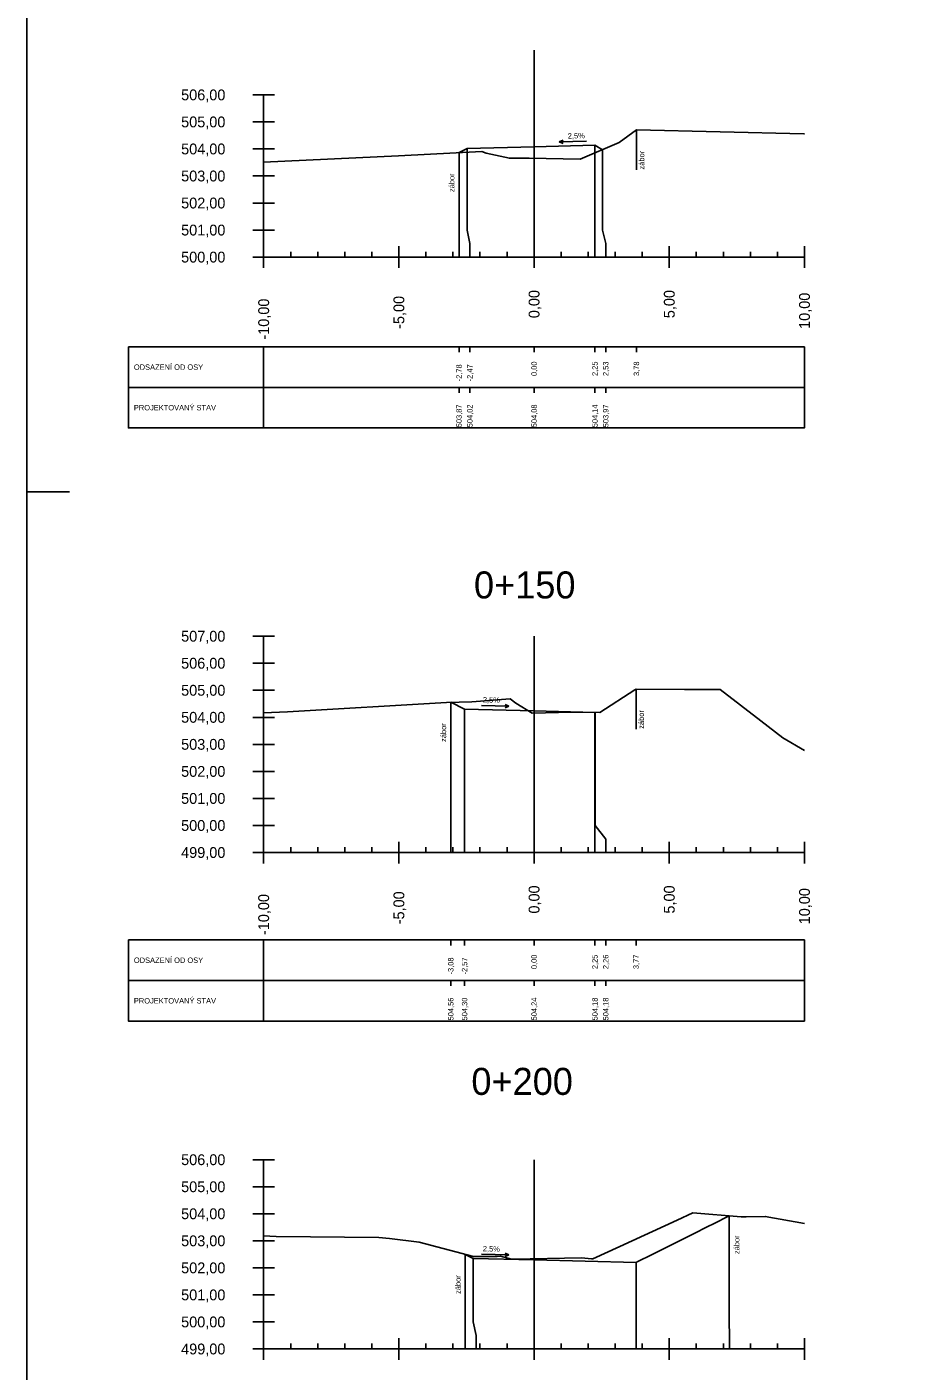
# Model space of a CAD drawing. Extents: x -631407 to -631215, y -1089700 to -1088598.
# Drawn here: x -631407.01 to -631374.65, y -1088857.16 to -1088807.44 of the extents above; entities that cross this region are included whole.
import ezdxf

# ---------------------------------------------------------------- set-up
doc = ezdxf.new("R2010")
doc.units = 0
for name, color, linetype in [('08_LEGENDA_HV', 7, 'Continuous'), ('59', 7, 'Continuous'), ('DTM-Breaklines', 7, 'Continuous'), ('NIVELETA_VYSKY', 7, 'Continuous'), ('REZ_BODY', 7, 'Continuous'), ('REZ_ODSTUPY', 7, 'Continuous'), ('REZ_POPIS', 7, 'Continuous'), ('REZ_RAMY', 7, 'Continuous'), ('REZ_STANICENI', 7, 'Continuous'), ('REZ_SVISLE', 7, 'Continuous'), ('REZ_TENKA', 7, 'Continuous'), ('REZ_TLUSTA', 7, 'Continuous'), ('TABULKA_POPIS', 7, 'Continuous'), ('TEREN', 7, 'Continuous'), ('zábor', 7, 'Continuous')]:
    doc.layers.add(name, color=color, linetype=linetype)

msp = doc.modelspace()

# ---------------------------------------------------------------- linework, layer by layer
at = {"layer": '08_LEGENDA_HV'}
msp.add_lwpolyline([(-631215.384, -1088943.435), (-631215.384, -1088765.235), (-631407.014, -1088765.235), (-631407.014, -1088943.435)], close=True, dxfattribs=at)
at = {"layer": '59'}
for p, q in [((-631398.658, -1088809.959), (-631397.858, -1088809.959)), ((-631398.258, -1088809.959), (-631398.258, -1088815.959)), ((-631398.658, -1088810.959), (-631397.858, -1088810.959)), ((-631398.658, -1088811.959), (-631397.858, -1088811.959)), ((-631398.658, -1088812.959), (-631397.858, -1088812.959)), ((-631398.658, -1088813.959), (-631397.858, -1088813.959)), ((-631398.658, -1088814.959), (-631397.858, -1088814.959)), ((-631398.658, -1088815.959), (-631397.858, -1088815.959)), ((-631398.658, -1088829.981), (-631397.858, -1088829.981)), ((-631398.258, -1088829.981), (-631398.258, -1088837.981)), ((-631398.658, -1088830.981), (-631397.858, -1088830.981)), ((-631398.658, -1088831.981), (-631397.858, -1088831.981)), ((-631398.658, -1088832.981), (-631397.858, -1088832.981)), ((-631398.658, -1088833.981), (-631397.858, -1088833.981)), ((-631398.658, -1088834.981), (-631397.858, -1088834.981)), ((-631398.658, -1088835.981), (-631397.858, -1088835.981)), ((-631398.658, -1088836.981), (-631397.858, -1088836.981)), ((-631398.658, -1088837.981), (-631397.858, -1088837.981)), ((-631398.658, -1088849.343), (-631397.858, -1088849.343)), ((-631398.258, -1088849.343), (-631398.258, -1088856.343)), ((-631398.658, -1088850.343), (-631397.858, -1088850.343)), ((-631398.658, -1088851.343), (-631397.858, -1088851.343)), ((-631398.658, -1088852.343), (-631397.858, -1088852.343)), ((-631398.658, -1088853.343), (-631397.858, -1088853.343)), ((-631398.658, -1088854.343), (-631397.858, -1088854.343)), ((-631398.658, -1088855.343), (-631397.858, -1088855.343)), ((-631398.658, -1088856.343), (-631397.858, -1088856.343))]:
    msp.add_line(p, q, dxfattribs=at)
at = {"layer": 'DTM-Breaklines'}
msp.add_line((-631407.014, -1088824.635), (-631405.434, -1088824.635), dxfattribs=at)
at = {"layer": 'REZ_RAMY'}
for p, q in [((-631398.258, -1088819.278), (-631398.258, -1088822.278)), ((-631391.034, -1088819.478), (-631391.034, -1088819.278)), ((-631390.634, -1088819.478), (-631390.634, -1088819.278)), ((-631388.258, -1088819.478), (-631388.258, -1088819.278)), ((-631386.008, -1088819.478), (-631386.008, -1088819.278)), ((-631385.608, -1088819.478), (-631385.608, -1088819.278)), ((-631384.474, -1088819.478), (-631384.474, -1088819.278)), ((-631403.258, -1088820.778), (-631378.258, -1088820.778)), ((-631391.034, -1088820.978), (-631391.034, -1088820.778)), ((-631390.634, -1088820.978), (-631390.634, -1088820.778)), ((-631388.258, -1088820.978), (-631388.258, -1088820.778)), ((-631386.008, -1088820.978), (-631386.008, -1088820.778)), ((-631385.608, -1088820.978), (-631385.608, -1088820.778)), ((-631403.258, -1088841.215), (-631403.258, -1088844.215)), ((-631398.258, -1088841.215), (-631398.258, -1088844.215)), ((-631391.339, -1088841.415), (-631391.339, -1088841.215)), ((-631390.828, -1088841.415), (-631390.828, -1088841.215)), ((-631388.258, -1088841.415), (-631388.258, -1088841.215)), ((-631386.008, -1088841.415), (-631386.008, -1088841.215)), ((-631385.608, -1088841.415), (-631385.608, -1088841.215)), ((-631384.488, -1088841.415), (-631384.488, -1088841.215)), ((-631403.258, -1088842.715), (-631378.258, -1088842.715)), ((-631391.339, -1088842.915), (-631391.339, -1088842.715)), ((-631390.828, -1088842.915), (-631390.828, -1088842.715)), ((-631388.258, -1088842.915), (-631388.258, -1088842.715)), ((-631386.008, -1088842.915), (-631386.008, -1088842.715)), ((-631385.608, -1088842.915), (-631385.608, -1088842.715))]:
    msp.add_line(p, q, dxfattribs=at)
for points in [[(-631403.258, -1088819.278), (-631403.258, -1088822.278), (-631378.258, -1088822.278), (-631378.258, -1088819.278)], [(-631403.258, -1088841.215), (-631403.258, -1088844.215), (-631378.258, -1088844.215), (-631378.258, -1088841.215)]]:
    msp.add_lwpolyline(points, close=True, dxfattribs=at)
at = {"layer": 'REZ_SVISLE'}
for points in [[(-631390.73, -1088811.94), (-631390.73, -1088814.959), (-631390.634, -1088815.459), (-631390.634, -1088815.959)], [(-631388.258, -1088811.878), (-631388.258, -1088814.959), (-631388.258, -1088815.459), (-631388.258, -1088815.959)], [(-631386.008, -1088811.821), (-631386.008, -1088814.959), (-631386.008, -1088815.459), (-631386.008, -1088815.959)], [(-631391.034, -1088812.091), (-631391.034, -1088814.959), (-631391.034, -1088815.459), (-631391.034, -1088815.959)], [(-631385.728, -1088811.99), (-631385.728, -1088814.959), (-631385.608, -1088815.459), (-631385.608, -1088815.959)], [(-631391.339, -1088832.426), (-631391.339, -1088836.981), (-631391.339, -1088837.481), (-631391.339, -1088837.981)], [(-631390.828, -1088832.682), (-631390.828, -1088836.981), (-631390.828, -1088837.481), (-631390.828, -1088837.981)], [(-631388.258, -1088832.746), (-631388.258, -1088836.981), (-631388.258, -1088837.481), (-631388.258, -1088837.981)], [(-631386.008, -1088832.802), (-631386.008, -1088836.981), (-631386.008, -1088837.481), (-631386.008, -1088837.981)], [(-631385.997, -1088832.797), (-631385.997, -1088836.981), (-631385.608, -1088837.481), (-631385.608, -1088837.981)], [(-631381.047, -1088851.421), (-631381.047, -1088855.343), (-631381.027, -1088855.843), (-631381.027, -1088856.343)], [(-631390.802, -1088852.844), (-631390.802, -1088855.343), (-631390.802, -1088855.843), (-631390.802, -1088856.343)], [(-631390.508, -1088852.991), (-631390.508, -1088855.343), (-631390.402, -1088855.843), (-631390.402, -1088856.343)], [(-631388.258, -1088853.047), (-631388.258, -1088855.343), (-631388.258, -1088855.843), (-631388.258, -1088856.343)], [(-631384.488, -1088853.141), (-631384.488, -1088855.343), (-631384.488, -1088855.843), (-631384.488, -1088856.343)]]:
    msp.add_lwpolyline(points, dxfattribs=at)
at = {"layer": 'REZ_TENKA'}
for p, q in [((-631397.258, -1088815.959), (-631397.258, -1088815.759)), ((-631396.258, -1088815.959), (-631396.258, -1088815.759)), ((-631395.258, -1088815.959), (-631395.258, -1088815.759)), ((-631394.258, -1088815.959), (-631394.258, -1088815.759)), ((-631392.258, -1088815.959), (-631392.258, -1088815.759)), ((-631391.258, -1088815.959), (-631391.258, -1088815.759)), ((-631390.258, -1088815.959), (-631390.258, -1088815.759)), ((-631389.258, -1088815.959), (-631389.258, -1088815.759)), ((-631387.258, -1088815.959), (-631387.258, -1088815.759)), ((-631386.258, -1088815.959), (-631386.258, -1088815.759)), ((-631385.258, -1088815.959), (-631385.258, -1088815.759)), ((-631384.258, -1088815.959), (-631384.258, -1088815.759)), ((-631382.258, -1088815.959), (-631382.258, -1088815.759)), ((-631381.258, -1088815.959), (-631381.258, -1088815.759)), ((-631380.258, -1088815.959), (-631380.258, -1088815.759)), ((-631379.258, -1088815.959), (-631379.258, -1088815.759)), ((-631397.258, -1088837.981), (-631397.258, -1088837.781)), ((-631396.258, -1088837.981), (-631396.258, -1088837.781)), ((-631395.258, -1088837.981), (-631395.258, -1088837.781)), ((-631394.258, -1088837.981), (-631394.258, -1088837.781)), ((-631392.258, -1088837.981), (-631392.258, -1088837.781)), ((-631391.258, -1088837.981), (-631391.258, -1088837.781)), ((-631390.258, -1088837.981), (-631390.258, -1088837.781)), ((-631389.258, -1088837.981), (-631389.258, -1088837.781)), ((-631387.258, -1088837.981), (-631387.258, -1088837.781)), ((-631386.258, -1088837.981), (-631386.258, -1088837.781)), ((-631385.258, -1088837.981), (-631385.258, -1088837.781)), ((-631384.258, -1088837.981), (-631384.258, -1088837.781)), ((-631382.258, -1088837.981), (-631382.258, -1088837.781)), ((-631381.258, -1088837.981), (-631381.258, -1088837.781)), ((-631380.258, -1088837.981), (-631380.258, -1088837.781)), ((-631379.258, -1088837.981), (-631379.258, -1088837.781)), ((-631397.258, -1088856.343), (-631397.258, -1088856.143)), ((-631396.258, -1088856.343), (-631396.258, -1088856.143)), ((-631395.258, -1088856.343), (-631395.258, -1088856.143)), ((-631394.258, -1088856.343), (-631394.258, -1088856.143)), ((-631392.258, -1088856.343), (-631392.258, -1088856.143)), ((-631391.258, -1088856.343), (-631391.258, -1088856.143)), ((-631390.258, -1088856.343), (-631390.258, -1088856.143)), ((-631389.258, -1088856.343), (-631389.258, -1088856.143)), ((-631387.258, -1088856.343), (-631387.258, -1088856.143)), ((-631386.258, -1088856.343), (-631386.258, -1088856.143)), ((-631385.258, -1088856.343), (-631385.258, -1088856.143)), ((-631384.258, -1088856.343), (-631384.258, -1088856.143)), ((-631382.258, -1088856.343), (-631382.258, -1088856.143)), ((-631381.258, -1088856.343), (-631381.258, -1088856.143)), ((-631380.258, -1088856.343), (-631380.258, -1088856.143)), ((-631379.258, -1088856.343), (-631379.258, -1088856.143))]:
    msp.add_line(p, q, dxfattribs=at)
at = {"layer": 'REZ_TLUSTA'}
for p, q in [((-631388.258, -1088808.311), (-631388.258, -1088815.959)), ((-631398.258, -1088816.359), (-631398.258, -1088815.559)), ((-631393.258, -1088816.359), (-631393.258, -1088815.559)), ((-631388.258, -1088816.359), (-631388.258, -1088815.559)), ((-631383.258, -1088816.359), (-631383.258, -1088815.559)), ((-631378.258, -1088816.359), (-631378.258, -1088815.559)), ((-631398.258, -1088815.959), (-631378.258, -1088815.959)), ((-631388.258, -1088829.981), (-631388.258, -1088837.981)), ((-631398.258, -1088838.381), (-631398.258, -1088837.581)), ((-631393.258, -1088838.381), (-631393.258, -1088837.581)), ((-631388.258, -1088838.381), (-631388.258, -1088837.581)), ((-631383.258, -1088838.381), (-631383.258, -1088837.581)), ((-631378.258, -1088838.381), (-631378.258, -1088837.581)), ((-631398.258, -1088837.981), (-631378.258, -1088837.981)), ((-631388.258, -1088849.343), (-631388.258, -1088856.343)), ((-631398.258, -1088856.743), (-631398.258, -1088855.943)), ((-631393.258, -1088856.743), (-631393.258, -1088855.943)), ((-631388.258, -1088856.743), (-631388.258, -1088855.943)), ((-631383.258, -1088856.743), (-631383.258, -1088855.943)), ((-631378.258, -1088856.743), (-631378.258, -1088855.943)), ((-631398.258, -1088856.343), (-631378.258, -1088856.343))]:
    msp.add_line(p, q, dxfattribs=at)
at = {"layer": 'TEREN'}
for points in [[(-631398.258, -1088812.452), (-631393.272, -1088812.209), (-631390.192, -1088812.047), (-631390.025, -1088812.118), (-631389.168, -1088812.305), (-631388.441, -1088812.303), (-631386.551, -1088812.341), (-631385.11, -1088811.726), (-631384.474, -1088811.256), (-631378.283, -1088811.395), (-631378.258, -1088811.395)], [(-631391.034, -1088812.091), (-631390.73, -1088811.94), (-631388.258, -1088811.878), (-631386.008, -1088811.821), (-631385.728, -1088811.99)], [(-631398.258, -1088832.81), (-631397.371, -1088832.776), (-631391.491, -1088832.43), (-631390.561, -1088832.404), (-631389.143, -1088832.293), (-631388.928, -1088832.457), (-631388.331, -1088832.829), (-631386.862, -1088832.789), (-631385.827, -1088832.798), (-631384.53, -1088831.967), (-631384.488, -1088831.942), (-631382.693, -1088831.951), (-631381.38, -1088831.957), (-631379.868, -1088833.109), (-631379.06, -1088833.742), (-631378.258, -1088834.205)], [(-631391.339, -1088832.426), (-631390.828, -1088832.682), (-631388.258, -1088832.746), (-631386.008, -1088832.802), (-631385.997, -1088832.797)], [(-631398.258, -1088852.164), (-631397.795, -1088852.184), (-631393.993, -1088852.218), (-631393.608, -1088852.261), (-631392.512, -1088852.393), (-631390.498, -1088852.924), (-631389.628, -1088852.924), (-631389.498, -1088852.914), (-631389.091, -1088853.025), (-631389.031, -1088853.025), (-631386.506, -1088852.976), (-631386.14, -1088853.011), (-631386.079, -1088853.007), (-631385.087, -1088852.557), (-631382.972, -1088851.575), (-631382.389, -1088851.312), (-631380.605, -1088851.457), (-631380.416, -1088851.458), (-631379.708, -1088851.441), (-631378.258, -1088851.704)], [(-631390.802, -1088852.844), (-631390.508, -1088852.991), (-631388.258, -1088853.047), (-631384.488, -1088853.141), (-631384.447, -1088853.12), (-631383.896, -1088852.844), (-631382.908, -1088852.355), (-631382.359, -1088852.083), (-631381.827, -1088851.814), (-631381.622, -1088851.712), (-631381.047, -1088851.421)]]:
    msp.add_lwpolyline(points, dxfattribs=at)
at = {"layer": 'zábor'}
for p, q in [((-631384.474, -1088811.256), (-631384.474, -1088812.737)), ((-631387.325, -1088811.698), (-631387.188, -1088811.634)), ((-631387.325, -1088811.698), (-631386.317, -1088811.673)), ((-631387.325, -1088811.698), (-631387.185, -1088811.756)), ((-631384.488, -1088831.942), (-631384.488, -1088833.422)), ((-631389.191, -1088832.566), (-631390.199, -1088832.541)), ((-631389.191, -1088832.566), (-631389.331, -1088832.624)), ((-631389.191, -1088832.566), (-631389.327, -1088832.502)), ((-631389.191, -1088852.867), (-631390.199, -1088852.842)), ((-631389.191, -1088852.867), (-631389.331, -1088852.925)), ((-631389.191, -1088852.867), (-631389.327, -1088852.803))]:
    msp.add_line(p, q, dxfattribs=at)

# ---------------------------------------------------------------- texts
at = {"layer": 'NIVELETA_VYSKY'}
for s, p in [('503,87', (-631390.934, -1088822.254)), ('504,02', (-631390.534, -1088822.254)), ('504,08', (-631388.158, -1088822.254)), ('504,14', (-631385.908, -1088822.254)), ('503,97', (-631385.508, -1088822.254)), ('504,56', (-631391.239, -1088844.191)), ('504,30', (-631390.728, -1088844.191)), ('504,24', (-631388.158, -1088844.191)), ('504,18', (-631385.908, -1088844.191)), ('504,18', (-631385.508, -1088844.191))]:
    msp.add_text(s, height=0.2, rotation=90, dxfattribs=at).set_placement(p)
at = {"layer": 'REZ_BODY'}
for s, p in [('0,00', (-631388.158, -1088820.357)), ('2,25', (-631385.908, -1088820.357)), ('2,53', (-631385.508, -1088820.357)), ('3,78', (-631384.374, -1088820.357)), ('-2,78', (-631390.934, -1088820.555)), ('-2,47', (-631390.534, -1088820.555)), ('0,00', (-631388.158, -1088842.294)), ('2,25', (-631385.908, -1088842.294)), ('2,26', (-631385.508, -1088842.294)), ('3,77', (-631384.388, -1088842.294)), ('-3,08', (-631391.239, -1088842.492)), ('-2,57', (-631390.728, -1088842.492))]:
    msp.add_text(s, height=0.2, rotation=90, dxfattribs=at).set_placement(p)
at = {"layer": 'REZ_ODSTUPY'}
for s, p in [('-5,00', (-631393.058, -1088818.614)), ('0,00', (-631388.058, -1088818.218)), ('5,00', (-631383.058, -1088818.218)), ('10,00', (-631378.058, -1088818.614)), ('-10,00', (-631398.058, -1088819.011)), ('0,00', (-631388.058, -1088840.239)), ('5,00', (-631383.058, -1088840.239)), ('-10,00', (-631398.058, -1088841.033)), ('-5,00', (-631393.058, -1088840.636)), ('10,00', (-631378.058, -1088840.636))]:
    msp.add_text(s, height=0.4, rotation=90, dxfattribs=at).set_placement(p)
at = {"layer": 'REZ_POPIS'}
for s, p in [('506,00', (-631401.31, -1088810.159)), ('505,00', (-631401.31, -1088811.159)), ('504,00', (-631401.31, -1088812.159)), ('503,00', (-631401.31, -1088813.159)), ('502,00', (-631401.31, -1088814.159)), ('501,00', (-631401.31, -1088815.159)), ('500,00', (-631401.31, -1088816.159)), ('507,00', (-631401.31, -1088830.181)), ('506,00', (-631401.31, -1088831.181)), ('505,00', (-631401.31, -1088832.181)), ('504,00', (-631401.31, -1088833.181)), ('503,00', (-631401.31, -1088834.181)), ('502,00', (-631401.31, -1088835.181)), ('501,00', (-631401.31, -1088836.181)), ('500,00', (-631401.31, -1088837.181)), ('499,00', (-631401.31, -1088838.181)), ('506,00', (-631401.31, -1088849.543)), ('505,00', (-631401.31, -1088850.543)), ('504,00', (-631401.31, -1088851.543)), ('503,00', (-631401.31, -1088852.543)), ('502,00', (-631401.31, -1088853.543)), ('501,00', (-631401.31, -1088854.543)), ('500,00', (-631401.31, -1088855.543)), ('499,00', (-631401.31, -1088856.543))]:
    msp.add_text(s, height=0.4, dxfattribs=at).set_placement(p)
at = {"layer": 'REZ_STANICENI'}
for s, p in [('0+150', (-631390.481, -1088828.584)), ('0+200', (-631390.577, -1088846.946))]:
    msp.add_text(s, height=1, dxfattribs=at).set_placement(p)
at = {"layer": 'TABULKA_POPIS'}
for s, p in [('ODSAZENÍ OD OSY', (-631403.058, -1088820.128)), ('PROJEKTOVANÝ STAV', (-631403.058, -1088821.628)), ('ODSAZENÍ OD OSY', (-631403.058, -1088842.065)), ('PROJEKTOVANÝ STAV', (-631403.058, -1088843.565))]:
    msp.add_text(s, height=0.2, dxfattribs=at).set_placement(p)
at = {"layer": 'zábor'}
for s, rotation, p in [('2,5%', 1.4321, (-631387.009, -1088811.577)), ('zábor', 90, (-631384.181, -1088812.719)), ('zábor', 90, (-631391.204, -1088813.555)), ('2,5%', 358.5679, (-631390.155, -1088832.429)), ('zábor', 90, (-631384.195, -1088833.405)), ('zábor', 90, (-631391.509, -1088833.89)), ('zábor', 90, (-631380.664, -1088852.835)), ('2,5%', 358.5679, (-631390.155, -1088852.73)), ('zábor', 90, (-631390.972, -1088854.307))]:
    msp.add_text(s, height=0.2, rotation=rotation, dxfattribs=at).set_placement(p)

doc.saveas('drawing.dxf')
